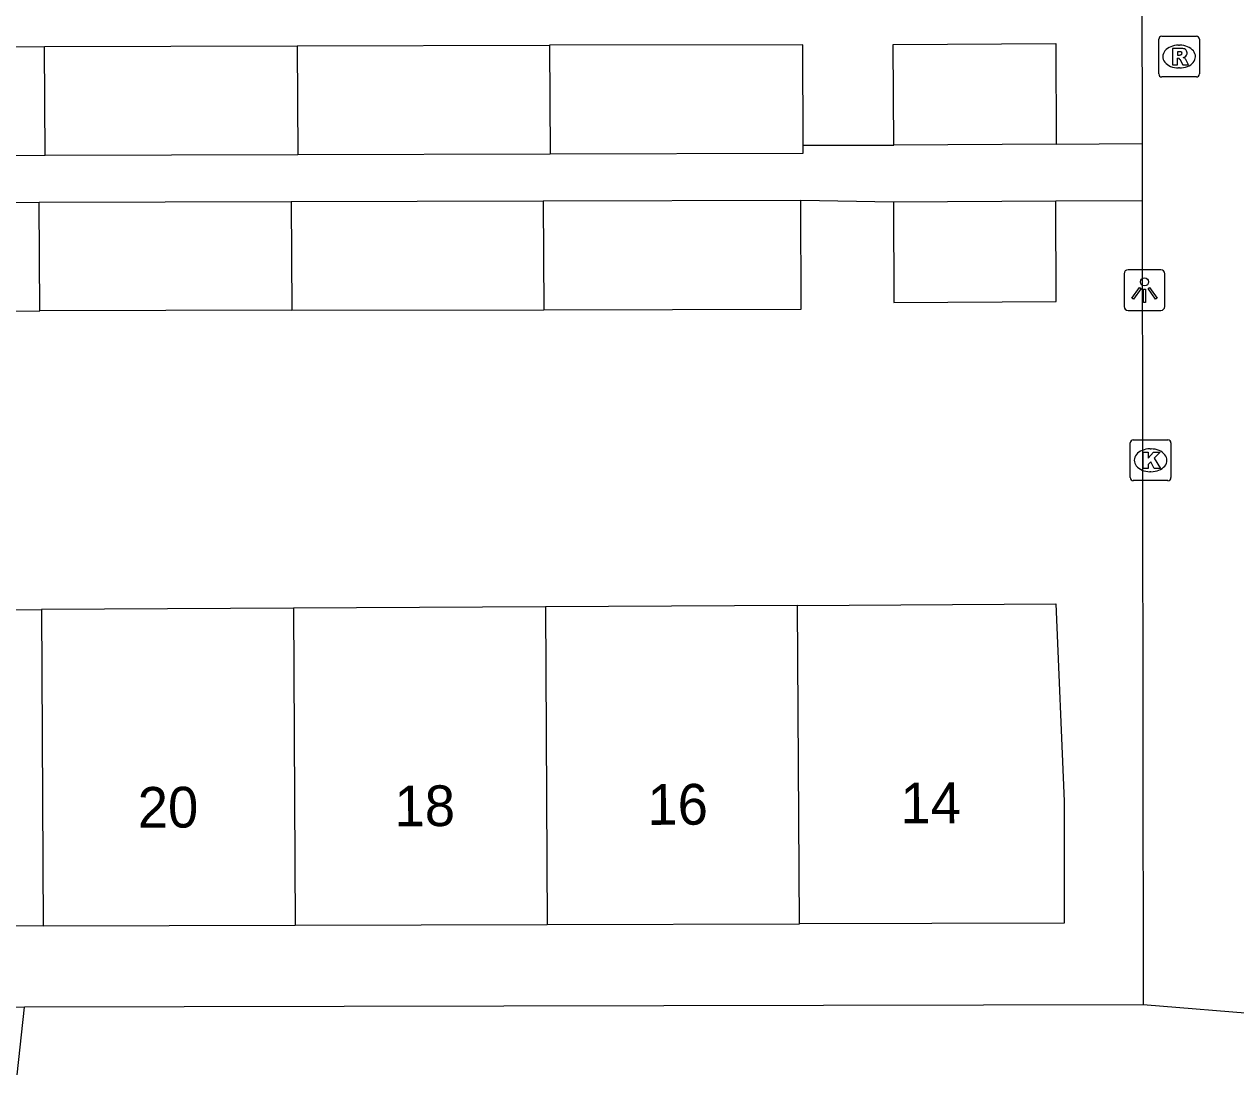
# Model space of a CAD drawing. Extents: x 160732 to 162105, y 387428 to 388479.
# Drawn here: x 161217.78 to 161247.53, y 387909.87 to 387935.67 of the extents above; entities that cross this region are included whole.
import ezdxf

# ---------------------------------------------------------------- set-up
doc = ezdxf.new("R2010")
doc.units = 0
for name, color, linetype in [('IMGEO_Kolk', 7, 'Continuous'), ('IMGEO_Lichtpunt', 7, 'Continuous'), ('IMGEO_Pand', 7, 'Continuous'), ('IMGEO_Pand_nummerreeks', 7, 'Continuous'), ('IMGEO_Rioolput', 7, 'Continuous'), ('IMGEO_Voetpad_open', 7, 'Continuous')]:
    doc.layers.add(name, color=color, linetype=linetype)

msp = doc.modelspace()

# ---------------------------------------------------------------- linework, layer by layer
at = {"layer": 'IMGEO_Kolk'}
for p, q in [((161244.939, 387924.531), (161244.939, 387925.383)), ((161245.014, 387925.457), (161245.866, 387925.457)), ((161245.94, 387925.383), (161245.94, 387924.531)), ((161245.427, 387925.237), (161245.452, 387925.237)), ((161245.866, 387924.457), (161245.014, 387924.457)), ((161245.45, 387924.677), (161245.425, 387924.677))]:
    msp.add_line(p, q, dxfattribs=at)
for points in [[(161244.939, 387924.531), (161244.939, 387925.383)], [(161245.014, 387925.457), (161245.866, 387925.457)], [(161245.94, 387925.383), (161245.94, 387924.531)], [(161245.26, 387925.157), (161245.383, 387925.157), (161245.383, 387925.006), (161245.513, 387925.157), (161245.677, 387925.157), (161245.531, 387925.006), (161245.684, 387924.757), (161245.532, 387924.757), (161245.447, 387924.921), (161245.383, 387924.854), (161245.383, 387924.757), (161245.26, 387924.757), (161245.26, 387925.157)], [(161245.866, 387924.457), (161245.014, 387924.457)]]:
    msp.add_lwpolyline(points, dxfattribs=at)
for centre, start, end in [((161245.016, 387925.381), 91.552, 178.448), ((161245.016, 387925.381), 91.552, 178.448), ((161245.864, 387925.381), 1.552, 88.448), ((161245.864, 387925.381), 1.552, 88.448), ((161245.016, 387924.533), 181.552, 268.448), ((161245.016, 387924.533), 181.552, 268.448), ((161245.864, 387924.533), 271.552, 358.448), ((161245.864, 387924.533), 271.552, 358.448)]:
    msp.add_arc(centre, 0.0765, start, end, dxfattribs=at)
for centre, major_axis, ratio, start_param, end_param in [((161245.426, 387924.957), (-0.387, 0.002), 0.722429, 4.712389, 7.853982), ((161245.451, 387924.957), (-0.39, 0.002), 0.717154, 1.570796, 4.712389)]:
    msp.add_ellipse(centre, major_axis=major_axis, ratio=ratio, start_param=start_param, end_param=end_param, dxfattribs=at)
at = {"layer": 'IMGEO_Lichtpunt'}
for p, q in [((161244.792, 387929.54), (161244.792, 387928.733)), ((161244.792, 387929.54), (161244.792, 387928.733)), ((161245.694, 387929.635), (161244.886, 387929.635)), ((161245.694, 387929.635), (161244.886, 387929.635)), ((161245.788, 387928.733), (161245.788, 387929.54)), ((161245.788, 387928.733), (161245.788, 387929.54)), ((161244.886, 387928.639), (161245.694, 387928.639)), ((161244.886, 387928.639), (161245.694, 387928.639))]:
    msp.add_line(p, q, dxfattribs=at)
for points in [[(161245.166, 387929.204), (161245.205, 387929.176), (161245.017, 387928.914), (161244.979, 387928.941), (161245.166, 387929.204)], [(161245.378, 387929.176), (161245.416, 387929.203), (161245.603, 387928.941), (161245.564, 387928.913), (161245.378, 387929.176)], [(161245.268, 387929.156), (161245.315, 387929.156), (161245.315, 387928.834), (161245.268, 387928.834), (161245.268, 387929.156)]]:
    msp.add_lwpolyline(points, dxfattribs=at)
msp.add_circle((161245.291, 387929.338), 0.0994, dxfattribs=at)
for centre, start, end in [((161244.886, 387929.54), 90, 180), ((161244.886, 387929.54), 90, 180), ((161245.694, 387929.54), 0, 90), ((161245.694, 387929.54), 0, 90), ((161244.886, 387928.733), 180, 270), ((161244.886, 387928.733), 180, 270), ((161245.694, 387928.733), 270, 0), ((161245.694, 387928.733), 270, 360)]:
    msp.add_arc(centre, 0.0946, start, end, dxfattribs=at)
at = {"layer": 'IMGEO_Pand'}
for points in [[(161218.284, 387935.118), (161224.486, 387935.133)], [(161224.486, 387935.133), (161230.685, 387935.148)], [(161224.486, 387935.133), (161224.501, 387932.468)], [(161236.911, 387932.693), (161236.905, 387935.163), (161230.685, 387935.148)], [(161230.685, 387935.148), (161230.7, 387932.483)], [(161239.136, 387932.699), (161239.123, 387935.168), (161243.11, 387935.191), (161243.124, 387932.722)], [(161212.085, 387935.103), (161218.284, 387935.118)], [(161218.299, 387932.453), (161218.284, 387935.118)], [(161218.299, 387932.453), (161224.501, 387932.468)], [(161224.501, 387932.468), (161230.7, 387932.483)], [(161230.7, 387932.483), (161236.912, 387932.498), (161236.911, 387932.693)], [(161243.124, 387932.722), (161239.136, 387932.699)], [(161212.1, 387932.439), (161218.299, 387932.453)], [(161218.151, 387931.29), (161214.222, 387931.281)], [(161214.222, 387931.281), (161214.228, 387928.616), (161218.166, 387928.625)], [(161224.339, 387931.305), (161218.151, 387931.29)], [(161218.166, 387928.625), (161218.151, 387931.29)], [(161230.528, 387931.32), (161224.339, 387931.305)], [(161224.339, 387931.305), (161224.354, 387928.64)], [(161236.853, 387931.335), (161230.528, 387931.32)], [(161230.528, 387931.32), (161230.543, 387928.655)], [(161230.543, 387928.655), (161236.86, 387928.67), (161236.853, 387931.335)], [(161239.124, 387931.294), (161239.137, 387928.83), (161243.125, 387928.853), (161243.111, 387931.317)], [(161243.111, 387931.317), (161239.124, 387931.294)], [(161224.354, 387928.64), (161218.166, 387928.625)], [(161224.354, 387928.64), (161230.543, 387928.655)], [(161212.02, 387921.256), (161218.208, 387921.291)], [(161224.396, 387921.325), (161218.208, 387921.291)], [(161218.208, 387921.291), (161218.252, 387913.527)], [(161230.584, 387921.36), (161224.396, 387921.325)], [(161224.396, 387921.325), (161224.44, 387913.542)], [(161236.772, 387921.395), (161230.584, 387921.36)], [(161230.584, 387921.36), (161230.628, 387913.557)], [(161236.772, 387921.395), (161243.11, 387921.43), (161243.319, 387916.587), (161243.319, 387913.587), (161236.816, 387913.571)], [(161236.816, 387913.571), (161236.772, 387921.395)], [(161218.252, 387913.527), (161212.064, 387913.513)], [(161218.252, 387913.527), (161224.44, 387913.542)], [(161224.44, 387913.542), (161230.628, 387913.557)], [(161230.628, 387913.557), (161236.816, 387913.571)]]:
    msp.add_lwpolyline(points, dxfattribs=at)
at = {"layer": 'IMGEO_Rioolput'}
for p, q in [((161245.64, 387934.445), (161245.64, 387935.297)), ((161245.715, 387935.371), (161246.567, 387935.371)), ((161246.128, 387935.151), (161246.153, 387935.151)), ((161246.641, 387935.297), (161246.641, 387934.445)), ((161246.151, 387934.591), (161246.126, 387934.591)), ((161246.567, 387934.371), (161245.715, 387934.371))]:
    msp.add_line(p, q, dxfattribs=at)
for points in [[(161245.64, 387934.445), (161245.64, 387935.297)], [(161245.715, 387935.371), (161246.567, 387935.371)], [(161246.641, 387935.297), (161246.641, 387934.445)], [(161246.229, 387935.069), (161245.977, 387935.071), (161245.977, 387934.671)], [(161246.155, 387934.99), (161246.101, 387934.99), (161246.101, 387934.909)], [(161246.101, 387934.909), (161246.153, 387934.909)], [(161245.977, 387934.671), (161246.101, 387934.671), (161246.101, 387934.833), (161246.112, 387934.833)], [(161246.159, 387934.804), (161246.23, 387934.671), (161246.37, 387934.671), (161246.305, 387934.797)], [(161246.567, 387934.371), (161245.715, 387934.371)]]:
    msp.add_lwpolyline(points, dxfattribs=at)
for centre, radius, start, end in [((161245.717, 387935.295), 0.0765, 91.552, 178.448), ((161245.717, 387935.295), 0.0765, 91.552, 178.448), ((161246.565, 387935.295), 0.0765, 1.552, 88.448), ((161246.565, 387935.295), 0.0765, 1.552, 88.448), ((161246.137, 387935.098), 0.19, 274.7715, 282.9687), ((161246.161, 387934.894), 0.0964, 77.0061, 93.1865), ((161246.175, 387934.951), 0.0378, 276.6634, 79.6772), ((161246.228, 387934.959), 0.109, 350.3612, 89.416), ((161246.226, 387934.959), 0.112, 277.5842, 350.9817), ((161246.21, 387934.744), 0.108, 29.5134, 73.7905), ((161246.111, 387934.78), 0.0533, 26.0293, 88.6989), ((161245.717, 387934.447), 0.0765, 181.552, 268.448), ((161245.717, 387934.447), 0.0765, 181.552, 268.448), ((161246.565, 387934.447), 0.0765, 271.552, 358.448), ((161246.565, 387934.447), 0.0765, 271.552, 358.448)]:
    msp.add_arc(centre, radius, start, end, dxfattribs=at)
for centre, major_axis, ratio, start_param, end_param in [((161246.127, 387934.871), (-0.387, 0.002), 0.722429, 4.712389, 7.853982), ((161246.152, 387934.871), (-0.39, 0.002), 0.717154, 1.570796, 4.712389)]:
    msp.add_ellipse(centre, major_axis=major_axis, ratio=ratio, start_param=start_param, end_param=end_param, dxfattribs=at)
at = {"layer": 'IMGEO_Voetpad_open'}
for points in [[(161245.206, 387950.779), (161245.221, 387939.638), (161245.226, 387936.499), (161245.231, 387932.734)], [(161236.911, 387932.693), (161239.136, 387932.699)], [(161243.124, 387932.722), (161245.231, 387932.734)], [(161245.231, 387932.734), (161245.233, 387931.329)], [(161239.124, 387931.294), (161236.853, 387931.335)], [(161245.233, 387931.329), (161243.111, 387931.317)], [(161245.233, 387931.329), (161245.26, 387911.586)], [(161217.792, 387911.526), (161168.317, 387911.418)], [(161217.608, 387909.867), (161217.792, 387911.526)], [(161245.26, 387911.586), (161217.792, 387911.526)], [(161248.263, 387911.338), (161245.26, 387911.586)]]:
    msp.add_lwpolyline(points, dxfattribs=at)

# ---------------------------------------------------------------- texts
at = {"layer": 'IMGEO_Pand_nummerreeks'}
for s, p in [('18', (161226.877, 387915.968)), ('16', (161233.087, 387916.003)), ('14', (161239.299, 387916.038)), ('20', (161220.573, 387915.932))]:
    msp.add_text(s, height=1, rotation=0.3205, dxfattribs=at).set_placement(p)

doc.saveas('drawing.dxf')
